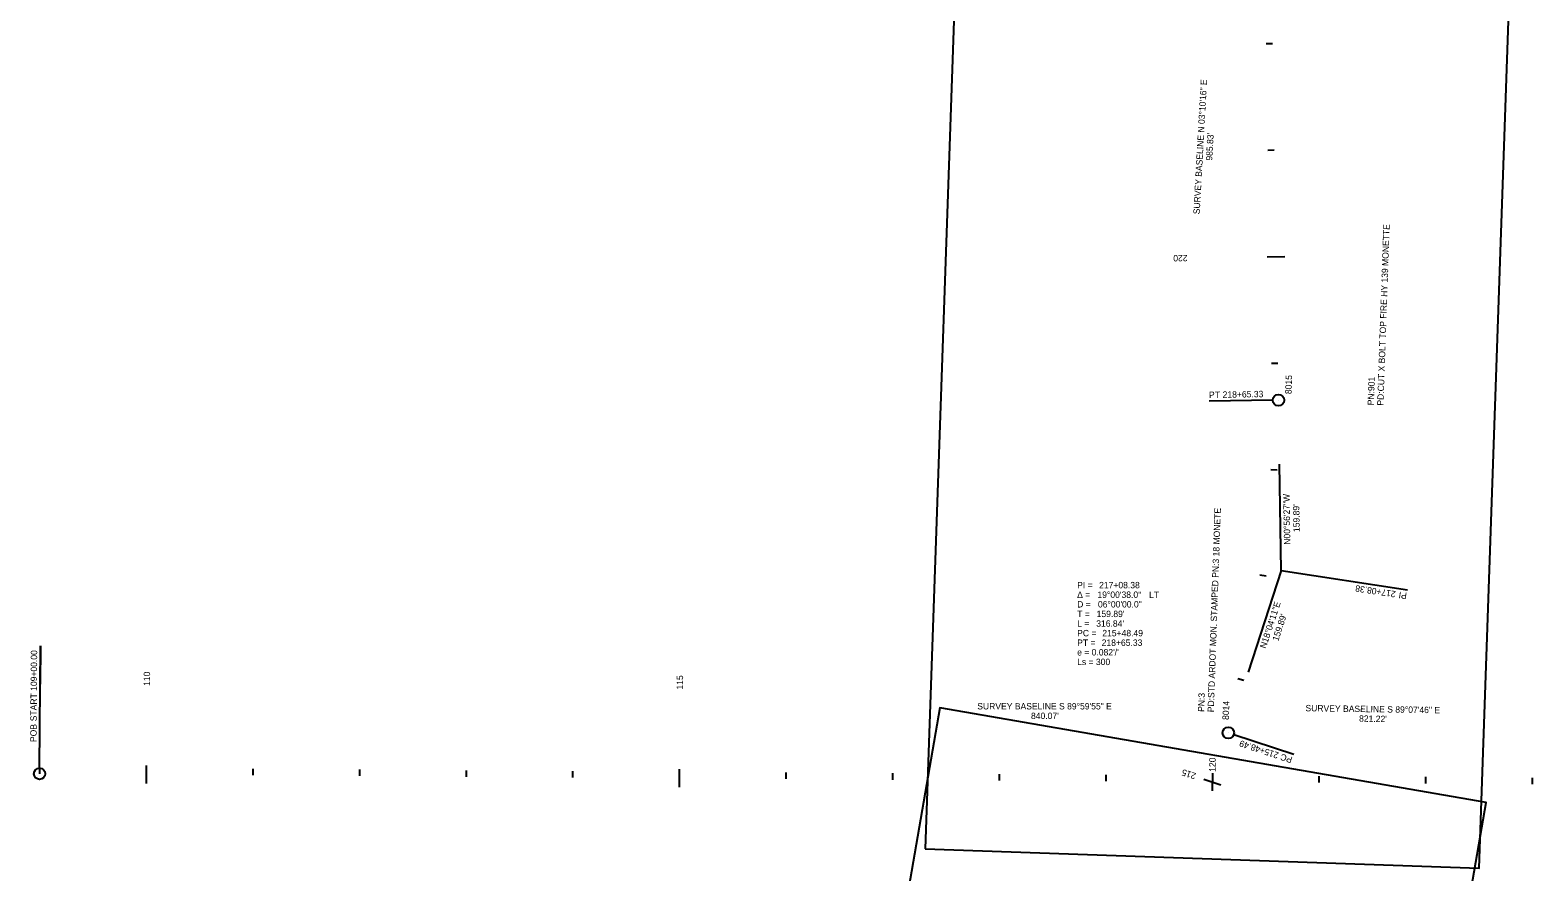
# Model space of a CAD drawing. Extents: x 1802363 to 1804577, y 572235 to 575339.
# Drawn here: x 1802363 to 1803778, y 573728 to 574517 of the extents above; entities that cross this region are included whole.
import ezdxf

# ---------------------------------------------------------------- set-up
doc = ezdxf.new("R2010")
doc.units = 0
for name, color, linetype in [('DSN_DRFT_Named-Boundary', 7, 'Continuous'), ('DSN_RDWY_Alignment Annotation', 7, 'Continuous'), ('S_BASELINE_ANNOT', 7, 'Continuous'), ('S_PRIMARY_CTL_ANNOT', 7, 'Continuous')]:
    doc.layers.add(name, color=color, linetype=linetype)

msp = doc.modelspace()

# ---------------------------------------------------------------- linework, layer by layer
at = {"layer": 'DSN_DRFT_Named-Boundary'}
for points in [[(1803202.9, 573749.5), (1803722.6, 573731.6), (1803777.5, 575320.8), (1803257.8, 575338.7)], [(1802946.7, 572323.9), (1803459.1, 572235.1), (1803729, 573792.9), (1803216.7, 573881.7)]]:
    msp.add_lwpolyline(points, close=True, dxfattribs=at)
at = {"layer": 'DSN_RDWY_Alignment Annotation'}
for p, q in [((1803522.7, 574504.8), (1803528.7, 574504.9)), ((1803524.3, 574404.9), (1803530.3, 574405)), ((1803523.5, 574304.8), (1803540.3, 574305.1)), ((1803527.6, 574204.9), (1803533.6, 574205)), ((1803528.8, 574170.2), (1803469.2, 574169.3)), ((1803469.2, 574169.3), (1803469.2, 574169.3)), ((1803534.2, 574170.3), (1803534.2, 574170.3)), ((1803536.8, 574010.5), (1803535.1, 574110.4)), ((1803527, 574105.3), (1803533, 574105)), ((1803536.8, 574010.5), (1803505.8, 573915.4)), ((1803536.8, 574010.5), (1803655.4, 573992.6)), ((1803516.7, 574006.5), (1803522.6, 574005.6)), ((1803655.4, 573992.6), (1803655.4, 573992.6)), ((1802372.2, 573825.3), (1802373, 573940)), ((1802373, 573940), (1802372.8, 573904)), ((1803496, 573909.4), (1803501.8, 573907.8)), ((1803487.2, 573858.4), (1803487.2, 573858.4)), ((1803492.3, 573856.8), (1803548.7, 573838.4)), ((1802372.2, 573826), (1802372.2, 573820)), ((1802472.2, 573827.7), (1802472.1, 573810.9)), ((1803548.7, 573838.4), (1803548.7, 573838.4)), ((1802372.2, 573820), (1802372.2, 573820)), ((1802572.2, 573824.6), (1802572.2, 573818.6)), ((1802672.2, 573823.9), (1802672.2, 573817.9)), ((1802772.2, 573823.2), (1802772.2, 573817.2)), ((1802872.2, 573822.5), (1802872.2, 573816.5)), ((1802972.2, 573824.2), (1802972.1, 573807.4)), ((1803072.2, 573821.1), (1803072.2, 573815.1)), ((1803172.2, 573820.4), (1803172.2, 573814.4)), ((1803272.2, 573819.7), (1803272.2, 573813.7)), ((1803372.2, 573819), (1803372.2, 573813)), ((1803464.2, 573815), (1803480.1, 573809.7)), ((1803472.2, 573820.7), (1803472.1, 573803.9)), ((1803572.2, 573817.7), (1803572.1, 573811.7)), ((1803672.2, 573817), (1803672.1, 573811)), ((1803772.2, 573816.3), (1803772.1, 573810.3))]:
    msp.add_line(p, q, dxfattribs=at)
for centre in [(1803534.2, 574170.3), (1803487.2, 573858.4), (1802372.2, 573820)]:
    msp.add_circle(centre, 5.34, dxfattribs=at)

# ---------------------------------------------------------------- texts
for s, rotation, p in [('220', 180.9408, (1803448.9, 574306.6)), ('8015', 88.0205, (1803546.4, 574175.9)), ('PT', 0.9408, (1803469.1, 574172.3)), ('218+65.33', 0.9408, (1803481.9, 574172.5)), ('N00°56\'27"W', 90.9408, (1803545.4, 574034.8)), ("159.89'", 90.9408, (1803554.2, 574046.7)), ('217+08.38', 171.4356, (1803644.5, 573991.2)), ('N18°04\'11"E', 71.9303, (1803522.3, 573937)), ('PI ', 171.4356, (1803655, 573989.6)), ("159.89'", 71.9303, (1803534, 573943.9)), ('109+00.00', 89.6021, (1802369.7, 573897.7)), ('110', 89.6021, (1802475.8, 573902.3)), ('115', 89.6021, (1802975.7, 573898.9)), ('START', 89.6021, (1802369.5, 573869.2)), ('8014', 88.0205, (1803487.6, 573870.4)), ('POB ', 89.6021, (1802369.4, 573849.7)), ('215+48.49', 161.9303, (1803535, 573839.7)), ('120', 89.6021, (1803475.2, 573821.8)), ('PC', 161.9303, (1803547.8, 573835.5)), ('215', 161.9303, (1803457.4, 573820.3))]:
    msp.add_text(s, height=6, rotation=rotation, dxfattribs=at).set_placement(p)
for s, p in [('PI = ', (1803345.4, 573993.9)), ('217+08.38', (1803366, 573993.9)), ('Δ = ', (1803345.4, 573984.9)), ('D = ', (1803345.4, 573975.9)), ('19°00\'38.0"', (1803364.4, 573984.9)), ('06°00\'00.0"', (1803364.9, 573975.9)), (' LT', (1803410.6, 573984.9)), ('T = ', (1803345.4, 573966.9)), ("159.89'", (1803363.7, 573966.9)), ('L = ', (1803345.4, 573957.9)), ('PC = ', (1803345.4, 573948.9)), ("316.84'", (1803363.3, 573957.9)), ('215+48.49', (1803369, 573948.9)), ('PT = ', (1803345.4, 573939.9)), ('218+65.33', (1803368.4, 573939.9)), ("e = 0.082'/'", (1803345.4, 573930.9)), ('Ls = 300', (1803345.4, 573921.9))]:
    msp.add_text(s, height=6, dxfattribs=at).set_placement(p)
at = {"layer": 'S_BASELINE_ANNOT'}
for s, rotation, p in [('SURVEY BASELINE N 03°10\'16" E', 86.829, (1803460.3, 574344.5)), ("985.83'", 86.829, (1803472.1, 574394.8)), ('SURVEY BASELINE S 89°59\'55" E', 359.9986, (1803251.7, 573880.3)), ('SURVEY BASELINE S 89°07\'46" E', 359.1294, (1803559.5, 573878.6)), ("840.07'", 359.9986, (1803302.1, 573871.3)), ("821.22'", 359.1294, (1803609.8, 573868.8))]:
    msp.add_text(s, height=6, rotation=rotation, dxfattribs=at).set_placement(p)
at = {"layer": 'S_PRIMARY_CTL_ANNOT'}
for s, p in [('PD:CUT X BOLT TOP FIRE HY 139 MONETTE', (1803632.7, 574165.1)), ('PN:901', (1803623.7, 574165.4)), ('PD:STD ARDOT MON. STAMPED PN:3 18 MONETE', (1803473.6, 573877.6)), ('PN:3', (1803464.6, 573877.9))]:
    msp.add_text(s, height=6, rotation=88.0205, dxfattribs=at).set_placement(p)

doc.saveas('drawing.dxf')
